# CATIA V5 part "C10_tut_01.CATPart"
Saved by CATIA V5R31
Part number: Part1
Bounding box of the stored display mesh (mm): x -88.601 to 88.601, y -88.601 to 152.104, z -258.54 to 20
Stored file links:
  D:\PROJECTS\Project 2021\US EDITION\CATIA V5 6R 2021\Resources\Tutorial Files\c10_catia_v5_6r2021_tut\C10_tut_01.CATPart
  J.rX
  E:\ashutosh\Academics\Catia\CATIA V5-6R2013_partfiles\Tutorials\c10_catia_v5-6r2013_tut\c10tut1.CATPart
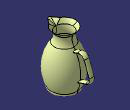
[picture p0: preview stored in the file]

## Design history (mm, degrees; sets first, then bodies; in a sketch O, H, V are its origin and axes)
Body1 (main body)
  Sketch1 on xy-plane, origin (0, 0, 0), H (1, 0, 0), V (0, 1, 0)
    circle A1 centre (0, 0) radius 45
    point P1 (-5, -44.7214)
    point P2 (5, -44.7214)
    distance P1 P2 = 10
    radius A1 = 45
    coincidence: P1 A1
    symmetry: P1 P2 V
  Plane1: type Offset, RefPlane xy-plane, Offset 20
  Sketch2 on Plane1, origin (0, 0, 20), H (1, 0, 0), V (0, 1, 0)
    arc A1 centre (0, 0) radius 60 from (30.5123, -51.6623) to (-30.5123, -51.6623) ccw
    arc A2 centre (0, -75) radius 10 from (-7.9335, -81.0876) to (7.9335, -81.0876) ccw
    point P1 (0, -75)
    line L1 (-7.9335, -81.0876) -> (-30.5123, -51.6623)
    point P2 (-7.9335, -81.0876)
    point P3 (-30.5123, -51.6623)
    point P4 (30.5123, -51.6623)
    point P5 (7.9335, -81.0876)
    line L2 (7.9335, -81.0876) -> (30.5123, -51.6623)
    radius A1 = 60
    radius A2 = 10
    distance O P1 = 75
    angle L1 L2 = 75
    coincidence: P1 V
    tangency: L1 A2
    symmetry: P3 P4 V, P2 P5 V, L1 L2 V
  Line1: type PtPt, FirstPoint vertex [element of Sketch2 | element of Sketch2], SecondPoint Sketch1.P2
  Loft1: Sections (Sketch1.A1; Sketch2), Guides Line1
  Sketch3 on yz-plane, origin (0, 0, 0), H (0, 1, 0), V (0, 0, 1)
    axis line L1 (0, 44.6071) -> (0, -361.7772)
    point P1 (0, 44.6071)
    arc A1 centre (96.9659, -18.0152) radius 55 from (45, 0) to (52.2225, -50) ccw
    point P4 (45, 0)
    point P5 (52.2225, -50)
    arc A2 centre (-106.3983, -163.4215) radius 195 from (52.2225, -50) to (70, -246.5398) cw
    point P7 (70, -246.5398)
    point P8 (54, -258.5398)
    arc A3 centre (0, -425) radius 175 from (54, -258.5398) to (0, -250) ccw
    point P9 (0, -425)
    point P10 (0, -250)
    line L2 (54, -258.5398) -> (64, -258.5398)
    arc A4 centre (64, -251.0398) radius 7.5 from (70, -246.5398) to (64, -258.5398) cw
    radius about axis P4 L1 = 45
    radius A1 = 55
    distance H P5 = 50
    radius A2 = 195
    radius about axis P7 L1 = 70
    distance H P10 = 250
    radius about axis P8 L1 = 54
    radius A3 = 175
    length L2 = 10
    radius A4 = 7.5
    coincidence: P1 V, P4 H, P10 L1, P9 V
    vertical: L1 V
    tangency: A1 A2, A4 L2
    horizontal: L2 H
  Revol1: Element1 Sketch3, Angle1 360
  Sketch4 on yz-plane, origin (0, 0, 0), H (0, 1, 0), V (0, 0, 1)
    point P1 (35.2741, -74.8693)
    line L1 (35.2741, -74.8693) -> (86.9572, -56.0582)
    line L2 (119, -71) -> (145.5066, -143.8262)
    line L3 (130.5647, -175.869) -> (63.8466, -200.1524)
    arc A1 centre (95.5077, -79.5505) radius 25 from (86.9572, -56.0582) to (119, -71) cw
    point P4 (119, -71)
    arc A2 centre (122.0142, -152.3767) radius 25 from (130.5647, -175.869) to (145.5066, -143.8262) ccw
    radius A1 = 25
    radius A2 = 25
    length L1 = 55
    distance H P4 = 71
    angle H L1 = 20
    distance P4 V = 119
    length L2 = 77.5
    length L3 = 71
    perpendicularity: L3 L2, L1 L2
    tangency: A1 L1, A1 L2, A2 L3, A2 L2
  Plane2: type Normal, Curve Sketch4, RefPoint Sketch4.P1, Ratio 0
  Sketch5 on Plane2, origin (0, 7.0853, 2.5788), H (1, 0, 0), V (0, -0.342, 0.9397)
    point P1 (0, -82.1273)
    ellipse A1 centre (0, -82.1273) semi-axes 12.5, 5 rotation 0
    point P2 (0, -87.1273)
    "Radius" A1 = 5
    "Radius" A1 = 12.5
    coincidence: P1 V, P2 V, A1 P2
  Sweep1: type Unspec, Profile Sketch5, Guide Sketch4
  Split1: ToCut Sweep1, Cutting Revol1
